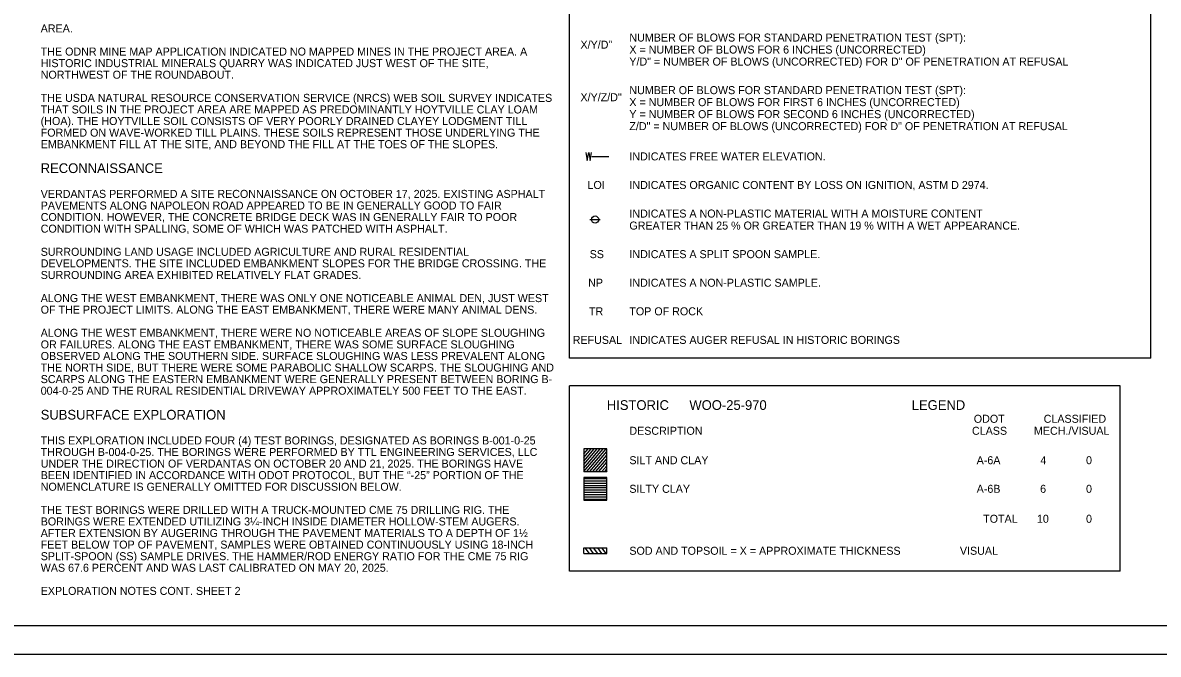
# Model space of a CAD drawing. Extents: x -59 to 43, y 0 to 22.
# Drawn here: x 2.1 to 21.96, y 0 to 11.05 of the extents above; entities that cross this region are included whole.
import ezdxf

# ---------------------------------------------------------------- set-up
doc = ezdxf.new("R2010")
doc.units = 0
for name, color, linetype in [('Default', 7, 'Continuous'), ('GT_Project_Cells', 7, 'Continuous'), ('GT_Project_Soil_Layers', 7, 'Continuous'), ('SH_Border', 7, 'Continuous'), ('SH_Cut_Line', 7, 'Continuous'), ('SH_Data', 7, 'Continuous'), ('SH_Text', 7, 'Continuous')]:
    doc.layers.add(name, color=color, linetype=linetype)

msp = doc.modelspace()

# ---------------------------------------------------------------- linework, layer by layer
at = {"layer": 'Default'}
for p, q in [((11.917, 3.506), (11.991, 3.595)), ((11.917, 3.443), (12.044, 3.595)), ((11.917, 3.381), (12.096, 3.595)), ((11.917, 3.319), (12.148, 3.595)), ((11.917, 3.257), (12.2, 3.595)), ((11.917, 3.195), (12.252, 3.595)), ((11.969, 3.195), (12.305, 3.595)), ((12.021, 3.195), (12.317, 3.547)), ((12.073, 3.195), (12.317, 3.485)), ((12.126, 3.195), (12.317, 3.422)), ((11.917, 3.195), (11.917, 3.195)), ((11.917, 3.192), (11.917, 3.192)), ((12.178, 3.195), (12.317, 3.36)), ((12.23, 3.195), (12.317, 3.298)), ((12.282, 3.195), (12.317, 3.236)), ((12.334, 3.195), (12.334, 3.195)), ((12.334, 3.192), (12.334, 3.192)), ((11.917, 3.095), (11.917, 3.095)), ((11.917, 3.075), (12.317, 3.075)), ((11.917, 3.035), (12.317, 3.035)), ((11.917, 2.995), (12.317, 2.995)), ((12.317, 3.095), (12.317, 3.095)), ((11.917, 2.955), (12.317, 2.955)), ((11.917, 2.915), (12.317, 2.915)), ((11.917, 2.875), (12.317, 2.875)), ((11.917, 2.835), (12.317, 2.835)), ((11.917, 2.795), (12.317, 2.795)), ((11.917, 2.755), (12.317, 2.755)), ((11.917, 2.715), (12.317, 2.715)), ((11.917, 2.695), (11.917, 2.695)), ((12.317, 2.695), (12.317, 2.695))]:
    msp.add_line(p, q, dxfattribs=at)
at = {"layer": 'GT_Project_Cells'}
msp.add_line((12.023, 7.605), (12.203, 7.605), dxfattribs=at)
msp.add_circle((12.113, 7.605), 0.0625, dxfattribs=at)
at = {"layer": 'GT_Project_Soil_Layers'}
for p, q in [((11.935, 1.861), (12.008, 1.761)), ((12.008, 1.861), (12.08, 1.761)), ((12.08, 1.861), (12.153, 1.761)), ((12.153, 1.861), (12.226, 1.761)), ((12.226, 1.861), (12.298, 1.761))]:
    msp.add_line(p, q, dxfattribs=at)
at = {"layer": 'SH_Border'}
msp.add_lwpolyline([(1.5, 21.5), (33.5, 21.5), (33.5, 0.5), (1.5, 0.5)], close=True, dxfattribs=at)
at = {"layer": 'SH_Cut_Line'}
msp.add_lwpolyline([(0, 0), (34, 0), (34, 22), (0, 22)], close=True, dxfattribs=at)
at = {"layer": 'SH_Data'}
for p, q in [((11.667, 5.18), (11.667, 21)), ((21.833, 5.18), (21.833, 21)), ((21.833, 5.18), (11.667, 5.18)), ((11.667, 1.455), (11.667, 4.695)), ((21.298, 4.695), (11.667, 4.695)), ((21.298, 1.455), (21.298, 4.695)), ((11.917, 1.761), (11.917, 1.861)), ((11.917, 1.861), (12.317, 1.861)), ((12.317, 1.761), (12.317, 1.861)), ((11.917, 1.761), (12.317, 1.761)), ((21.298, 1.455), (11.667, 1.455))]:
    msp.add_line(p, q, dxfattribs=at)
for points in [[(11.917, 3.195), (12.317, 3.195), (12.317, 3.595), (11.917, 3.595)], [(11.917, 2.695), (12.317, 2.695), (12.317, 3.095), (11.917, 3.095)]]:
    msp.add_lwpolyline(points, close=True, dxfattribs=at)
at = {"layer": 'SH_Text'}
msp.add_line((12.054, 8.711), (12.354, 8.711), dxfattribs=at)
msp.add_lwpolyline([(11.953, 8.781), (11.974, 8.641), (12.001, 8.781), (12.029, 8.641), (12.051, 8.781)], dxfattribs=at)

# ---------------------------------------------------------------- texts
at = {"layer": 'SH_Data'}
for s, p in [('X/Y/D"', (11.857, 10.595)), ('X/Y/Z/D"', (11.857, 9.675)), ('LOI', (11.98, 8.14)), ('SS', (12.018, 6.93)), ('NP', (11.992, 6.43)), ('TR', (12.006, 5.93)), ('REFUSAL', (11.721, 5.43))]:
    msp.add_text(s, height=0.14, dxfattribs=at).set_placement(p)
at = {"layer": 'SH_Text'}
for s, height, p in [('AREA. ', 0.14, (2.417, 10.879)), ('NUMBER OF BLOWS FOR STANDARD PENETRATION TEST (SPT):', 0.14, (12.712, 10.719)), ('THE ODNR MINE MAP APPLICATION INDICATED NO MAPPED MINES IN THE PROJECT AREA. A ', 0.14, (2.417, 10.474)), ('X = NUMBER OF BLOWS FOR 6 INCHES (UNCORRECTED)', 0.14, (12.712, 10.509)), ('HISTORIC INDUSTRIAL MINERALS QUARRY WAS INDICATED JUST WEST OF THE SITE, ', 0.14, (2.417, 10.271)), ('Y/D" = NUMBER OF BLOWS (UNCORRECTED) FOR D" OF PENETRATION AT REFUSAL', 0.14, (12.712, 10.299)), ('NORTHWEST OF THE ROUNDABOUT.', 0.14, (2.417, 10.069)), ('NUMBER OF BLOWS FOR STANDARD PENETRATION TEST (SPT):', 0.14, (12.712, 9.799)), ('THE USDA NATURAL RESOURCE CONSERVATION SERVICE (NRCS) WEB SOIL SURVEY INDICATES ', 0.14, (2.417, 9.664)), ('X = NUMBER OF BLOWS FOR FIRST 6 INCHES (UNCORRECTED)', 0.14, (12.712, 9.589)), ('THAT SOILS IN THE PROJECT AREA ARE MAPPED AS PREDOMINANTLY HOYTVILLE CLAY LOAM ', 0.14, (2.417, 9.461)), ('(HOA). THE HOYTVILLE SOIL CONSISTS OF VERY POORLY DRAINED CLAYEY LODGMENT TILL ', 0.14, (2.417, 9.259)), ('Y = NUMBER OF BLOWS FOR SECOND 6 INCHES (UNCORRECTED)', 0.14, (12.712, 9.379)), ('FORMED ON WAVE-WORKED TILL PLAINS. THESE SOILS REPRESENT THOSE UNDERLYING THE ', 0.14, (2.417, 9.056)), ('Z/D" = NUMBER OF BLOWS (UNCORRECTED) FOR D" OF PENETRATION AT REFUSAL', 0.14, (12.712, 9.169)), ('EMBANKMENT FILL AT THE SITE, AND BEYOND THE FILL AT THE TOES OF THE SLOPES.', 0.14, (2.417, 8.854)), ('INDICATES FREE WATER ELEVATION.', 0.14, (12.712, 8.64)), ('RECONNAISSANCE', 0.17, (2.417, 8.419)), ('INDICATES ORGANIC CONTENT BY LOSS ON IGNITION, ASTM D 2974.', 0.14, (12.712, 8.14)), ('VERDANTAS PERFORMED A SITE RECONNAISSANCE ON OCTOBER 17, 2025. EXISTING ASPHALT ', 0.14, (2.417, 7.984)), ('PAVEMENTS ALONG NAPOLEON ROAD APPEARED TO BE IN GENERALLY GOOD TO FAIR ', 0.14, (2.417, 7.781)), ('INDICATES A NON-PLASTIC MATERIAL WITH A MOISTURE CONTENT', 0.14, (12.712, 7.64)), ('CONDITION. HOWEVER, THE CONCRETE BRIDGE DECK WAS IN GENERALLY FAIR TO POOR ', 0.14, (2.417, 7.579)), ('GREATER THAN 25 % OR GREATER THAN 19 % WITH A WET APPEARANCE.', 0.14, (12.712, 7.43)), ('CONDITION WITH SPALLING, SOME OF WHICH WAS PATCHED WITH ASPHALT. ', 0.14, (2.417, 7.376)), ('SURROUNDING LAND USAGE INCLUDED AGRICULTURE AND RURAL RESIDENTIAL ', 0.14, (2.417, 6.971)), ('INDICATES A SPLIT SPOON SAMPLE.', 0.14, (12.712, 6.93)), ('DEVELOPMENTS. THE SITE INCLUDED EMBANKMENT SLOPES FOR THE BRIDGE CROSSING. THE ', 0.14, (2.417, 6.769)), ('SURROUNDING AREA EXHIBITED RELATIVELY FLAT GRADES.', 0.14, (2.417, 6.566)), ('INDICATES A NON-PLASTIC SAMPLE.', 0.14, (12.712, 6.43)), ('ALONG THE WEST EMBANKMENT, THERE WAS ONLY ONE NOTICEABLE ANIMAL DEN, JUST WEST ', 0.14, (2.417, 6.161)), ('OF THE PROJECT LIMITS. ALONG THE EAST EMBANKMENT, THERE WERE MANY ANIMAL DENS.', 0.14, (2.417, 5.959)), ('TOP OF ROCK', 0.14, (12.712, 5.93)), ('ALONG THE WEST EMBANKMENT, THERE WERE NO NOTICEABLE AREAS OF SLOPE SLOUGHING ', 0.14, (2.417, 5.554)), ('INDICATES AUGER REFUSAL IN HISTORIC BORINGS', 0.14, (12.712, 5.43)), ('OR FAILURES. ALONG THE EAST EMBANKMENT, THERE WAS SOME SURFACE SLOUGHING ', 0.14, (2.417, 5.351)), ('OBSERVED ALONG THE SOUTHERN SIDE. SURFACE SLOUGHING WAS LESS PREVALENT ALONG ', 0.14, (2.417, 5.149)), ('THE NORTH SIDE, BUT THERE WERE SOME PARABOLIC SHALLOW SCARPS. THE SLOUGHING AND ', 0.14, (2.417, 4.946)), ('SCARPS ALONG THE EASTERN EMBANKMENT WERE GENERALLY PRESENT BETWEEN BORING B-', 0.14, (2.417, 4.744)), ('004-0-25 AND THE RURAL RESIDENTIAL DRIVEWAY APPROXIMATELY 500 FEET TO THE EAST.', 0.14, (2.417, 4.541)), ('HISTORIC  ', 0.17, (12.318, 4.275)), ('WOO-25-970', 0.17, (13.762, 4.275)), ('LEGEND', 0.17, (17.651, 4.275)), ('SUBSURFACE EXPLORATION', 0.17, (2.417, 4.106)), ('ODOT', 0.14, (18.736, 4.05)), ('CLASSIFIED', 0.14, (19.958, 4.05)), ('DESCRIPTION', 0.14, (12.712, 3.84)), ('CLASS', 0.14, (18.704, 3.84)), ('MECH./VISUAL', 0.14, (19.788, 3.84)), ('THIS EXPLORATION INCLUDED FOUR (4) TEST BORINGS, DESIGNATED AS BORINGS B-001-0-25 ', 0.14, (2.417, 3.671)), ('THROUGH B-004-0-25. THE BORINGS WERE PERFORMED BY TTL ENGINEERING SERVICES, LLC ', 0.14, (2.417, 3.469)), ('UNDER THE DIRECTION OF VERDANTAS ON OCTOBER 20 AND 21, 2025. THE BORINGS HAVE ', 0.14, (2.417, 3.266)), ('SILT AND CLAY', 0.14, (12.712, 3.325)), ('A-6A', 0.14, (18.786, 3.325)), ('4', 0.14, (19.9, 3.325)), ('0', 0.14, (20.699, 3.325)), ('BEEN IDENTIFIED IN ACCORDANCE WITH ODOT PROTOCOL, BUT THE “-25” PORTION OF THE ', 0.14, (2.417, 3.064)), ('NOMENCLATURE IS GENERALLY OMITTED FOR DISCUSSION BELOW. ', 0.14, (2.417, 2.861)), ('SILTY CLAY', 0.14, (12.712, 2.825)), ('A-6B', 0.14, (18.786, 2.825)), ('6', 0.14, (19.896, 2.825)), ('0', 0.14, (20.699, 2.825)), ('THE TEST BORINGS WERE DRILLED WITH A TRUCK-MOUNTED CME 75 DRILLING RIG. THE ', 0.14, (2.417, 2.456)), ('BORINGS WERE EXTENDED UTILIZING 3¼-INCH INSIDE DIAMETER HOLLOW-STEM AUGERS. ', 0.14, (2.417, 2.254)), ('   TOTAL   ', 0.14, (18.744, 2.301)), ('10', 0.14, (19.84, 2.301)), ('0', 0.14, (20.699, 2.301)), ('AFTER EXTENSION BY AUGERING THROUGH THE PAVEMENT MATERIALS TO A DEPTH OF 1½ ', 0.14, (2.417, 2.051)), ('FEET BELOW TOP OF PAVEMENT, SAMPLES WERE OBTAINED CONTINUOUSLY USING 18-INCH ', 0.14, (2.417, 1.849)), ('SPLIT-SPOON (SS) SAMPLE DRIVES. THE HAMMER/ROD ENERGY RATIO FOR THE CME 75 RIG ', 0.14, (2.417, 1.646)), ('SOD AND TOPSOIL = X = APPROXIMATE THICKNESS', 0.14, (12.712, 1.741)), ('   VISUAL  ', 0.14, (18.337, 1.741)), ('WAS 67.6 PERCENT AND WAS LAST CALIBRATED ON MAY 20, 2025.', 0.14, (2.417, 1.444)), ('EXPLORATION NOTES CONT. SHEET 2', 0.14, (2.417, 1.039))]:
    msp.add_text(s, height=height, dxfattribs=at).set_placement(p)

doc.saveas('drawing.dxf')
